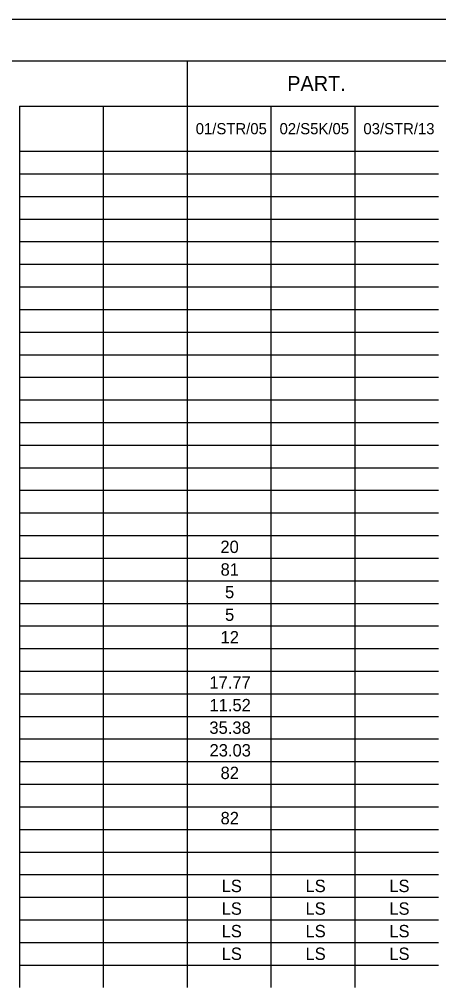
# Model space of a CAD drawing. Extents: x 0 to 34, y 0 to 22.
# Drawn here: x 9.6 to 14.66, y 10.33 to 22 of the extents above; entities that cross this region are included whole.
import ezdxf

# ---------------------------------------------------------------- set-up
doc = ezdxf.new("R2010")
doc.units = 0
for name, color, linetype in [('Default', 7, 'Continuous'), ('SH_Border', 7, 'Continuous'), ('SH_Cut_Line', 7, 'Continuous')]:
    doc.layers.add(name, color=color, linetype=linetype)

msp = doc.modelspace()

# ---------------------------------------------------------------- linework, layer by layer
at = {"layer": 'Default'}
for p, q in [((9.598, 21.5), (11.623, 21.5)), ((11.623, 21.5), (12.635, 21.5)), ((11.623, 21.5), (11.623, 21.227)), ((12.635, 21.5), (13.647, 21.5)), ((13.647, 21.5), (14.659, 21.5)), ((11.623, 21.227), (11.623, 20.955)), ((9.598, 20.955), (11.623, 20.955)), ((9.598, 20.955), (9.598, 20.682)), ((10.61, 20.955), (10.61, 20.682)), ((11.623, 20.955), (12.635, 20.955)), ((11.623, 20.955), (11.623, 20.682)), ((12.635, 20.955), (13.647, 20.955)), ((12.635, 20.955), (12.635, 20.682)), ((13.647, 20.955), (14.659, 20.955)), ((13.647, 20.955), (13.647, 20.682)), ((9.598, 20.682), (9.598, 20.41)), ((10.61, 20.682), (10.61, 20.41)), ((11.623, 20.682), (11.623, 20.41)), ((12.635, 20.682), (12.635, 20.41)), ((13.647, 20.682), (13.647, 20.41)), ((9.598, 20.41), (11.623, 20.41)), ((9.598, 20.41), (9.598, 20.137)), ((10.61, 20.41), (10.61, 20.137)), ((11.623, 20.41), (12.635, 20.41)), ((11.623, 20.41), (11.623, 20.137)), ((12.635, 20.41), (13.647, 20.41)), ((12.635, 20.41), (12.635, 20.137)), ((13.647, 20.41), (14.659, 20.41)), ((13.647, 20.41), (13.647, 20.137)), ((9.598, 20.137), (11.623, 20.137)), ((9.598, 20.137), (9.598, 18.775)), ((10.61, 20.137), (10.61, 18.775)), ((11.623, 20.137), (12.635, 20.137)), ((11.623, 20.137), (11.623, 18.775)), ((12.635, 20.137), (13.647, 20.137)), ((12.635, 20.137), (12.635, 18.775)), ((13.647, 20.137), (14.659, 20.137)), ((13.647, 20.137), (13.647, 18.775)), ((9.598, 19.865), (11.623, 19.865)), ((11.623, 19.865), (12.635, 19.865)), ((12.635, 19.865), (13.647, 19.865)), ((13.647, 19.865), (14.659, 19.865)), ((9.598, 19.592), (11.623, 19.592)), ((11.623, 19.592), (12.635, 19.592)), ((12.635, 19.592), (13.647, 19.592)), ((13.647, 19.592), (14.659, 19.592)), ((9.598, 19.32), (11.623, 19.32)), ((11.623, 19.32), (12.635, 19.32)), ((12.635, 19.32), (13.647, 19.32)), ((13.647, 19.32), (14.659, 19.32)), ((9.598, 19.047), (11.623, 19.047)), ((11.623, 19.047), (12.635, 19.047)), ((12.635, 19.047), (13.647, 19.047)), ((13.647, 19.047), (14.659, 19.047)), ((9.598, 18.775), (11.623, 18.775)), ((9.598, 18.775), (9.598, 18.23)), ((10.61, 18.775), (10.61, 18.23)), ((11.623, 18.775), (12.635, 18.775)), ((11.623, 18.775), (11.623, 18.23)), ((12.635, 18.775), (13.647, 18.775)), ((12.635, 18.775), (12.635, 18.23)), ((13.647, 18.775), (14.659, 18.775)), ((13.647, 18.775), (13.647, 18.23)), ((9.598, 18.502), (11.623, 18.502)), ((11.623, 18.502), (12.635, 18.502)), ((12.635, 18.502), (13.647, 18.502)), ((13.647, 18.502), (14.659, 18.502)), ((9.598, 18.23), (11.623, 18.23)), ((9.598, 18.23), (9.598, 17.957)), ((10.61, 18.23), (10.61, 17.957)), ((11.623, 18.23), (12.635, 18.23)), ((11.623, 18.23), (11.623, 17.957)), ((12.635, 18.23), (13.647, 18.23)), ((12.635, 18.23), (12.635, 17.957)), ((13.647, 18.23), (14.659, 18.23)), ((13.647, 18.23), (13.647, 17.957)), ((9.598, 17.957), (11.623, 17.957)), ((9.598, 17.957), (9.598, 17.685)), ((10.61, 17.957), (10.61, 17.685)), ((11.623, 17.957), (12.635, 17.957)), ((11.623, 17.957), (11.623, 17.685)), ((12.635, 17.957), (13.647, 17.957)), ((12.635, 17.957), (12.635, 17.685)), ((13.647, 17.957), (14.659, 17.957)), ((13.647, 17.957), (13.647, 17.685)), ((9.598, 17.685), (11.623, 17.685)), ((9.598, 17.685), (9.598, 17.412)), ((10.61, 17.685), (10.61, 17.412)), ((11.623, 17.685), (12.635, 17.685)), ((11.623, 17.685), (11.623, 17.412)), ((12.635, 17.685), (13.647, 17.685)), ((12.635, 17.685), (12.635, 17.412)), ((13.647, 17.685), (14.659, 17.685)), ((13.647, 17.685), (13.647, 17.412)), ((9.598, 17.412), (11.623, 17.412)), ((9.598, 17.412), (9.598, 17.139)), ((10.61, 17.412), (10.61, 17.139)), ((11.623, 17.412), (12.635, 17.412)), ((11.623, 17.412), (11.623, 17.139)), ((12.635, 17.412), (13.647, 17.412)), ((12.635, 17.412), (12.635, 17.139)), ((13.647, 17.412), (14.659, 17.412)), ((13.647, 17.412), (13.647, 17.139)), ((9.598, 17.139), (11.623, 17.139)), ((9.598, 17.139), (9.598, 16.867)), ((10.61, 17.139), (10.61, 16.867)), ((11.623, 17.139), (12.635, 17.139)), ((11.623, 17.139), (11.623, 16.867)), ((12.635, 17.139), (13.647, 17.139)), ((12.635, 17.139), (12.635, 16.867)), ((13.647, 17.139), (14.659, 17.139)), ((13.647, 17.139), (13.647, 16.867)), ((9.598, 16.867), (11.623, 16.867)), ((9.598, 16.867), (9.598, 16.322)), ((10.61, 16.867), (10.61, 16.322)), ((11.623, 16.867), (12.635, 16.867)), ((11.623, 16.867), (11.623, 16.322)), ((12.635, 16.867), (13.647, 16.867)), ((12.635, 16.867), (12.635, 16.322)), ((13.647, 16.867), (14.659, 16.867)), ((13.647, 16.867), (13.647, 16.322)), ((9.598, 16.594), (11.623, 16.594)), ((11.623, 16.594), (12.635, 16.594)), ((12.635, 16.594), (13.647, 16.594)), ((13.647, 16.594), (14.659, 16.594)), ((9.598, 16.322), (11.623, 16.322)), ((9.598, 16.322), (9.598, 16.049)), ((10.61, 16.322), (10.61, 16.049)), ((11.623, 16.322), (12.635, 16.322)), ((11.623, 16.322), (11.623, 16.049)), ((12.635, 16.322), (13.647, 16.322)), ((12.635, 16.322), (12.635, 16.049)), ((13.647, 16.322), (14.659, 16.322)), ((13.647, 16.322), (13.647, 16.049)), ((9.598, 16.049), (11.623, 16.049)), ((9.598, 16.049), (9.598, 15.777)), ((10.61, 16.049), (10.61, 15.777)), ((11.623, 16.049), (12.635, 16.049)), ((11.623, 16.049), (11.623, 15.777)), ((12.635, 16.049), (13.647, 16.049)), ((12.635, 16.049), (12.635, 15.777)), ((13.647, 16.049), (14.659, 16.049)), ((13.647, 16.049), (13.647, 15.777)), ((9.598, 15.777), (11.623, 15.777)), ((9.598, 15.777), (9.598, 15.504)), ((10.61, 15.777), (10.61, 15.504)), ((11.623, 15.777), (12.635, 15.777)), ((11.623, 15.777), (11.623, 15.504)), ((12.635, 15.777), (13.647, 15.777)), ((12.635, 15.777), (12.635, 15.504)), ((13.647, 15.777), (14.659, 15.777)), ((13.647, 15.777), (13.647, 15.504)), ((9.598, 15.504), (11.623, 15.504)), ((9.598, 15.504), (9.598, 14.959)), ((10.61, 15.504), (10.61, 14.959)), ((11.623, 15.504), (12.635, 15.504)), ((11.623, 15.504), (11.623, 14.959)), ((12.635, 15.504), (13.647, 15.504)), ((12.635, 15.504), (12.635, 14.959)), ((13.647, 15.504), (14.659, 15.504)), ((13.647, 15.504), (13.647, 14.959)), ((9.598, 15.232), (11.623, 15.232)), ((11.623, 15.232), (12.635, 15.232)), ((12.635, 15.232), (13.647, 15.232)), ((13.647, 15.232), (14.659, 15.232)), ((9.598, 14.959), (11.623, 14.959)), ((9.598, 14.959), (9.598, 14.687)), ((10.61, 14.959), (10.61, 14.687)), ((11.623, 14.959), (12.635, 14.959)), ((11.623, 14.959), (11.623, 14.687)), ((12.635, 14.959), (13.647, 14.959)), ((12.635, 14.959), (12.635, 14.687)), ((13.647, 14.959), (14.659, 14.959)), ((13.647, 14.959), (13.647, 14.687)), ((9.598, 14.687), (11.623, 14.687)), ((9.598, 14.687), (9.598, 14.414)), ((10.61, 14.687), (10.61, 14.414)), ((11.623, 14.687), (12.635, 14.687)), ((11.623, 14.687), (11.623, 14.414)), ((12.635, 14.687), (13.647, 14.687)), ((12.635, 14.687), (12.635, 14.414)), ((13.647, 14.687), (14.659, 14.687)), ((13.647, 14.687), (13.647, 14.414)), ((9.598, 14.414), (11.623, 14.414)), ((9.598, 14.414), (9.598, 14.142)), ((10.61, 14.414), (10.61, 14.142)), ((11.623, 14.414), (12.635, 14.414)), ((11.623, 14.414), (11.623, 14.142)), ((12.635, 14.414), (13.647, 14.414)), ((12.635, 14.414), (12.635, 14.142)), ((13.647, 14.414), (14.659, 14.414)), ((13.647, 14.414), (13.647, 14.142)), ((9.598, 14.142), (11.623, 14.142)), ((9.598, 14.142), (9.598, 11.961)), ((10.61, 14.142), (10.61, 11.961)), ((11.623, 14.142), (12.635, 14.142)), ((11.623, 14.142), (11.623, 11.961)), ((12.635, 14.142), (13.647, 14.142)), ((12.635, 14.142), (12.635, 11.961)), ((13.647, 14.142), (14.659, 14.142)), ((13.647, 14.142), (13.647, 11.961)), ((9.598, 13.869), (11.623, 13.869)), ((11.623, 13.869), (12.635, 13.869)), ((12.635, 13.869), (13.647, 13.869)), ((13.647, 13.869), (14.659, 13.869)), ((9.598, 13.597), (11.623, 13.597)), ((11.623, 13.597), (12.635, 13.597)), ((12.635, 13.597), (13.647, 13.597)), ((13.647, 13.597), (14.659, 13.597)), ((9.598, 13.324), (11.623, 13.324)), ((11.623, 13.324), (12.635, 13.324)), ((12.635, 13.324), (13.647, 13.324)), ((13.647, 13.324), (14.659, 13.324)), ((9.598, 13.052), (11.623, 13.052)), ((11.623, 13.052), (12.635, 13.052)), ((12.635, 13.052), (13.647, 13.052)), ((13.647, 13.052), (14.659, 13.052)), ((9.598, 12.779), (11.623, 12.779)), ((11.623, 12.779), (12.635, 12.779)), ((12.635, 12.779), (13.647, 12.779)), ((13.647, 12.779), (14.659, 12.779)), ((9.598, 12.506), (11.623, 12.506)), ((11.623, 12.506), (12.635, 12.506)), ((12.635, 12.506), (13.647, 12.506)), ((13.647, 12.506), (14.659, 12.506)), ((9.598, 12.234), (11.623, 12.234)), ((11.623, 12.234), (12.635, 12.234)), ((12.635, 12.234), (13.647, 12.234)), ((13.647, 12.234), (14.659, 12.234)), ((9.598, 11.961), (11.623, 11.961)), ((9.598, 11.961), (9.598, 11.689)), ((10.61, 11.961), (10.61, 11.689)), ((11.623, 11.961), (12.635, 11.961)), ((11.623, 11.961), (11.623, 11.689)), ((12.635, 11.961), (13.647, 11.961)), ((12.635, 11.961), (12.635, 11.689)), ((13.647, 11.961), (14.659, 11.961)), ((13.647, 11.961), (13.647, 11.689)), ((9.598, 11.689), (11.623, 11.689)), ((9.598, 11.689), (9.598, 10.599)), ((10.61, 11.689), (10.61, 10.599)), ((11.623, 11.689), (12.635, 11.689)), ((11.623, 11.689), (11.623, 10.599)), ((12.635, 11.689), (13.647, 11.689)), ((12.635, 11.689), (12.635, 10.599)), ((13.647, 11.689), (14.659, 11.689)), ((13.647, 11.689), (13.647, 10.599)), ((9.598, 11.416), (11.623, 11.416)), ((11.623, 11.416), (12.635, 11.416)), ((12.635, 11.416), (13.647, 11.416)), ((13.647, 11.416), (14.659, 11.416)), ((9.598, 11.144), (11.623, 11.144)), ((11.623, 11.144), (12.635, 11.144)), ((12.635, 11.144), (13.647, 11.144)), ((13.647, 11.144), (14.659, 11.144)), ((9.598, 10.871), (11.623, 10.871)), ((11.623, 10.871), (12.635, 10.871)), ((12.635, 10.871), (13.647, 10.871)), ((13.647, 10.871), (14.659, 10.871)), ((9.598, 10.599), (11.623, 10.599)), ((9.598, 10.599), (9.598, 10.326)), ((10.61, 10.599), (10.61, 10.326)), ((11.623, 10.599), (12.635, 10.599)), ((11.623, 10.599), (11.623, 10.326)), ((12.635, 10.599), (13.647, 10.599)), ((12.635, 10.599), (12.635, 10.326)), ((13.647, 10.599), (14.659, 10.599)), ((13.647, 10.599), (13.647, 10.326))]:
    msp.add_line(p, q, dxfattribs=at)
at = {"layer": 'SH_Border'}
msp.add_lwpolyline([(1.5, 21.5), (33.5, 21.5), (33.5, 0.5), (1.5, 0.5)], close=True, dxfattribs=at)
at = {"layer": 'SH_Cut_Line'}
msp.add_lwpolyline([(0, 0), (34, 0), (34, 22), (0, 22)], close=True, dxfattribs=at)

# ---------------------------------------------------------------- texts
at = {"layer": 'Default'}
for s, height, p in [('PART.', 0.1791, (12.832, 21.138)), ('01/STR/05', 0.1343, (11.727, 20.615)), ('02/S5K/05', 0.1343, (12.739, 20.615)), ('03/STR/13', 0.1343, (13.751, 20.615)), ('20', 0.1492, (12.025, 15.566)), ('81', 0.1492, (12.027, 15.293)), ('5', 0.149, (12.081, 15.021)), ('5', 0.149, (12.081, 14.748)), ('12', 0.1492, (12.027, 14.476)), ('17.77', 0.1492, (11.892, 13.931)), ('11.52', 0.1492, (11.893, 13.658)), ('35.38', 0.1492, (11.892, 13.386)), ('23.03', 0.1492, (11.894, 13.113)), ('82', 0.1492, (12.027, 12.841)), ('82', 0.1492, (12.027, 12.296)), ('LS', 0.1492, (12.04, 11.478)), ('LS', 0.1492, (13.052, 11.478)), ('LS', 0.1492, (14.064, 11.478)), ('LS', 0.1492, (12.04, 11.205)), ('LS', 0.1492, (13.052, 11.205)), ('LS', 0.1492, (14.064, 11.205)), ('LS', 0.1492, (12.04, 10.933)), ('LS', 0.1492, (13.052, 10.933)), ('LS', 0.1492, (14.064, 10.933)), ('LS', 0.1492, (12.04, 10.66)), ('LS', 0.1492, (13.052, 10.66)), ('LS', 0.1492, (14.064, 10.66))]:
    msp.add_text(s, height=height, dxfattribs=at).set_placement(p)

doc.saveas('drawing.dxf')
